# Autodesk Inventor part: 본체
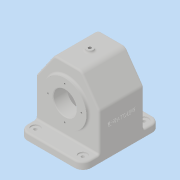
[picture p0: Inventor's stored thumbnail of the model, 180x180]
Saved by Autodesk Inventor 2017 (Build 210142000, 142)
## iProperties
Part Number: 본체
Material: 일반
Document SubType Name: Modeling
Designer: MRC
Density: 1 g/cm^3
Appearance: 기본값
Author: MRC
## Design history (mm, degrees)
sketch "스케치1"
  geometry: L1 (-23.491, 57)-(-55, 12); L2 (-55, 12)-(-55, -65); L3 (-55, -65)-(55, -65); L4 (55, -65)-(55, 12); L5 (55, 12)-(23.491, 57); L6 (23.491, 57)-(-23.491, 57); 2 further points
  constraints: 12 end point, 3 perpendicular, 1 midpoint, 1 vertical, 1 vertical alignment
  dimensions: "d0" = 77 distance of L1.end L2.end; "d1" = 35 deg angle of L2 L1; "d2" = 35 deg angle of L5 L4; "d3" = 122 distance between parallel lines of L6 L3; "d4" = 77 distance of L3.end L4.end; "d5" = 110 distance of L2.end L3.end; "d6" = 65 distance from line of point (0, 0) L3
extrude "돌출1" new body sketch "스케치1" stored distance "d7" = 77; taper "d8" = 0 deg
feature "쉘1" dims "d9" = 5
sketch "스케치2"
  geometry: L1 (0, 0)-(110, 0) reference; L2 (110, 0)-(110, 28.5); L3 (110, 28.5)-(0, 28.5); L4 (0, 28.5)-(0, 0); L5 (31.509, 0)-(0, 0) reference; L6 (0, -77)-(0, 0) reference; 1 further point
  constraints: 6 end point, 2 perpendicular, 1 collinear, 1 point on line, 1 vertical
  dimensions: "d10" = 67 distance from line of L3 point (55, -38.5)
extrude "돌출2" join sketch "스케치2" distance "d11" = 12; taper "d12" = 0 deg
sketch "스케치3"
  geometry: C1 r 6 at (23.491, 38.5); 1 further point
  constraints: 1 centre point, 1 coincident
  dimensions: "d13" = 6 radius of C1
extrude "돌출3" join sketch "스케치3" distance "d14" = 4; taper "d15" = 0 deg
sketch "스케치4"
  geometry: C1 r 37.5 at (0, 0); 1 further point
  constraints: 1 centre point, 1 coincident
  dimensions: "d16" = 75 diameter of C1
extrude "돌출4" join sketch "스케치4" distance "d17" = 5; taper "d18" = 0 deg
sketch "스케치5"
  geometry: C1 r 31 at (0, 0); 1 further point
  constraints: 1 centre point, 1 coincident
  dimensions: "d19" = 62 diameter of C1
extrude "돌출5" join sketch "스케치5" distance "d20" = 10; taper "d21" = 0 deg
node "작업 평면1"
sketch "스케치6"
  geometry: C1 r 27 at (0, 0); 1 further point
  constraints: 1 centre point, 1 coincident
  dimensions: "d23" = 54 diameter of C1
extrude "돌출6" join sketch "스케치6" stored distance "d24" = 10; taper "d25" = 45 deg
hole "구멍1" diameter "d28" = 40; stored, may be unused: countersink angle "d32" = 90 deg, drill point angle "d34" = 118 deg; dims "d26" = 10, "d27" = 10, "d29" = 6, "d30" = 4, "d31" = 2, "d33" = 24
hole "구멍2" diameter "d37" = 40; stored, may be unused: countersink angle "d41" = 90 deg, drill point angle "d43" = 118 deg; dims "d35" = 10, "d36" = 10, "d38" = 6, "d39" = 4, "d40" = 2, "d42" = 15
fillet "모깎기1" dims "d44" = 14
sketch "스케치7"
  geometry: A1 r 14 centre (14, 91.5) between (14, 105.5) and (0, 91.5) reference; A2 r 14 centre (96, 91.5) between (110, 91.5) and (96, 105.5) reference; A3 r 14 centre (96, -14.5) between (96, -28.5) and (110, -14.5) reference; A4 r 14 centre (14, -14.5) between (0, -14.5) and (14, -28.5) reference; 5 further points
  constraints: 4 coincident
hole "구멍3" sketch "스케치7" at (14, 91.5), (96, 91.5), (96, -14.5), (14, -14.5) diameter "d45" = 5.5; stored, may be unused: countersink angle "d49" = 90 deg, drill point angle "d51" = 118 deg; dims "d46" = 6, "d47" = 15, "d48" = 2, "d50" = 15
hole "구멍4" diameter "d54" = 5.188; stored, may be unused: countersink angle "d58" = 90 deg, drill point angle "d60" = 118 deg; dims "d52" = 10, "d53" = 10, "d55" = 20, "d56" = 15, "d57" = 2, "d59" = 20
sketch "스케치8"
  geometry: A1 r 29 centre (0, 0) between (0, 29) and (-29, 0); 3 further points
  constraints: 4 point on circle, 1 centre point, 1 coincident
  dimensions: "d61" = 58 diameter of A1
hole "구멍5" sketch "스케치8" at (0, 29), (-29, 0), (0, -29), (29, 0) diameter "d62" = 2.459; stored, may be unused: countersink angle "d66" = 90 deg, drill point angle "d68" = 118 deg; dims "d63" = 6, "d64" = 15, "d65" = 2, "d67" = 8
sketch "스케치9"
  geometry: A1 r 26 centre (0, 0) between (0, 26) and (-26, 0); 3 further points
  constraints: 4 point on circle, 1 centre point, 1 coincident
  dimensions: "d69" = 52 diameter of A1
hole "구멍6" sketch "스케치9" at (0, 26), (-26, 0), (0, -26), (26, 0) diameter "d70" = 2.459; stored, may be unused: countersink angle "d74" = 90 deg, drill point angle "d76" = 118 deg; dims "d71" = 6, "d72" = 15, "d73" = 2, "d75" = 8
node "작업 평면2"
sketch "스케치10"
  geometry: L1 (-53, 67)-(-65, 67) reference; L2 (-65, -53)-(-65, 53) reference; L3 (-53, 38.5)-(12, 38.5) reference; 2 further points
  constraints: 1 other
  dimensions: "d79" = 50 distance from line of L2 point (-15, 0); "d87" = 28.5 distance between parallel lines of L3 L1 (derived); "d88" = 38.5 distance from line of point (-15, 0) L3
feature "엠보싱1" sketch "스케치10" dims "d80" = 0.5, "d81" = 0
fillet "모깎기2" dims "d82" = 10
fillet "모깎기3" dims "d83" = 3
chamfer "모따기1" distance "d84" = 1; stored, may be unused: second distance "d85" = 2, angle "d86" = 45 deg
node "솔리드1"
mirror "미러1"
other parameters: "d22" = -24, "d77" = 63.25
